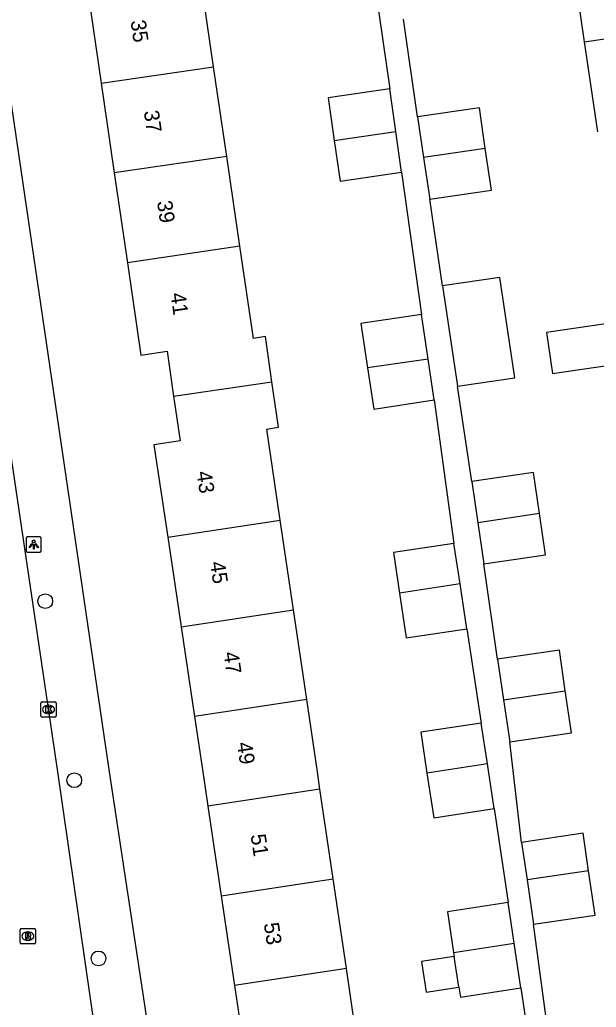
# Model space of a CAD drawing. Extents: x 159053 to 160041, y 380450 to 381422.
# Drawn here: x 159329.7 to 159367.8, y 380984.4 to 381049.8 of the extents above; entities that cross this region are included whole.
import ezdxf

# ---------------------------------------------------------------- set-up
doc = ezdxf.new("R2010")
doc.units = 0
for name, color, linetype in [('IMGEO_Boom', 7, 'Continuous'), ('IMGEO_Kolk', 7, 'Continuous'), ('IMGEO_Lichtpunt', 7, 'Continuous'), ('IMGEO_Pand', 7, 'Continuous'), ('IMGEO_Pand_nummerreeks', 7, 'Continuous'), ('IMGEO_Rijbaan_lokaal_open', 7, 'Continuous'), ('IMGEO_Rioolput', 7, 'Continuous'), ('IMGEO_Voetpad_open', 7, 'Continuous')]:
    doc.layers.add(name, color=color, linetype=linetype)

msp = doc.modelspace()

# ---------------------------------------------------------------- linework, layer by layer
at = {"layer": 'IMGEO_Boom'}
for centre in [(159331.342, 381011.301), (159333.264, 380999.452), (159334.871, 380987.659)]:
    msp.add_circle(centre, 0.489, dxfattribs=at)
at = {"layer": 'IMGEO_Kolk'}
for p, q in [((159331.061, 381003.707), (159331.061, 381004.559)), ((159331.136, 381004.633), (159331.988, 381004.633)), ((159331.549, 381004.413), (159331.574, 381004.413)), ((159332.062, 381004.559), (159332.062, 381003.707)), ((159331.572, 381003.853), (159331.547, 381003.853)), ((159331.988, 381003.633), (159331.136, 381003.633))]:
    msp.add_line(p, q, dxfattribs=at)
for points in [[(159331.061, 381003.707), (159331.061, 381004.559)], [(159331.136, 381004.633), (159331.988, 381004.633)], [(159331.382, 381004.333), (159331.505, 381004.333), (159331.505, 381004.182), (159331.635, 381004.333), (159331.799, 381004.333), (159331.653, 381004.182), (159331.806, 381003.933), (159331.654, 381003.933), (159331.569, 381004.097), (159331.505, 381004.03), (159331.505, 381003.933), (159331.382, 381003.933), (159331.382, 381004.333)], [(159332.062, 381004.559), (159332.062, 381003.707)], [(159331.988, 381003.633), (159331.136, 381003.633)]]:
    msp.add_lwpolyline(points, dxfattribs=at)
for centre, start, end in [((159331.138, 381004.557), 91.55205, 178.44795), ((159331.138, 381004.557), 91.55205, 178.44795), ((159331.986, 381004.557), 1.55205, 88.44795), ((159331.986, 381004.557), 1.55205, 88.44795), ((159331.138, 381003.709), 181.55205, 268.44795), ((159331.138, 381003.709), 181.55205, 268.44795), ((159331.986, 381003.709), 271.55205, 358.44795), ((159331.986, 381003.709), 271.55205, 358.44795)]:
    msp.add_arc(centre, 0.0765, start, end, dxfattribs=at)
for centre, major_axis, ratio, start_param, end_param in [((159331.548, 381004.133), (-0.387, 0.002), 0.722429, 4.712389, 7.853982), ((159331.573, 381004.133), (-0.39, 0.002), 0.717154, 1.570796, 4.712389)]:
    msp.add_ellipse(centre, major_axis=major_axis, ratio=ratio, start_param=start_param, end_param=end_param, dxfattribs=at)
at = {"layer": 'IMGEO_Lichtpunt'}
for p, q in [((159330.084, 381015.453), (159330.084, 381014.646)), ((159330.084, 381015.453), (159330.084, 381014.646)), ((159330.986, 381015.548), (159330.178, 381015.548)), ((159330.986, 381015.548), (159330.178, 381015.548)), ((159331.08, 381014.646), (159331.08, 381015.453)), ((159331.08, 381014.646), (159331.08, 381015.453)), ((159330.178, 381014.552), (159330.986, 381014.552)), ((159330.178, 381014.552), (159330.986, 381014.552))]:
    msp.add_line(p, q, dxfattribs=at)
for points in [[(159330.458, 381015.117), (159330.497, 381015.089), (159330.309, 381014.827), (159330.271, 381014.854), (159330.458, 381015.117)], [(159330.56, 381015.069), (159330.607, 381015.069), (159330.607, 381014.747), (159330.56, 381014.747), (159330.56, 381015.069)], [(159330.67, 381015.089), (159330.708, 381015.116), (159330.895, 381014.854), (159330.856, 381014.826), (159330.67, 381015.089)]]:
    msp.add_lwpolyline(points, dxfattribs=at)
msp.add_circle((159330.583, 381015.251), 0.0994, dxfattribs=at)
for centre, start, end in [((159330.178, 381015.453), 90, 180), ((159330.178, 381015.453), 90, 180), ((159330.986, 381015.453), 0, 90), ((159330.986, 381015.453), 0, 90), ((159330.178, 381014.646), 180, 270), ((159330.178, 381014.646), 180, 270), ((159330.986, 381014.646), 270, 0), ((159330.986, 381014.646), 270, 360)]:
    msp.add_arc(centre, 0.0946, start, end, dxfattribs=at)
at = {"layer": 'IMGEO_Pand'}
for points in [[(159366.155, 381054.257), (159367.026, 381048.302)], [(159342.489, 381046.664), (159341.62, 381052.601)], [(159334.178, 381051.506), (159335.047, 381045.569)], [(159367.026, 381048.302), (159374.491, 381049.393)], [(159367.026, 381048.302), (159367.898, 381042.344)], [(159335.047, 381045.569), (159342.489, 381046.664)], [(159343.358, 381040.727), (159342.489, 381046.664)], [(159335.047, 381045.569), (159335.916, 381039.632)], [(159354.151, 381045.198), (159350.069, 381044.601), (159350.482, 381041.775)], [(159354.553, 381042.375), (159354.151, 381045.198)], [(159360.479, 381041.259), (159360.084, 381043.953), (159355.997, 381043.355)], [(159355.997, 381043.355), (159356.392, 381040.661)], [(159350.482, 381041.775), (159354.553, 381042.375)], [(159354.937, 381039.685), (159354.553, 381042.375)], [(159350.482, 381041.775), (159350.874, 381039.091), (159354.937, 381039.685)], [(159360.479, 381041.259), (159356.392, 381040.661)], [(159356.797, 381037.893), (159360.884, 381038.491), (159360.479, 381041.259)], [(159343.358, 381040.727), (159335.916, 381039.632)], [(159344.226, 381034.79), (159343.358, 381040.727)], [(159356.392, 381040.661), (159356.797, 381037.893)], [(159335.916, 381039.632), (159336.784, 381033.695)], [(159344.226, 381034.79), (159336.784, 381033.695)], [(159346.351, 381025.823), (159345.915, 381028.807), (159345.122, 381028.669), (159344.226, 381034.79)], [(159336.784, 381033.695), (159337.678, 381027.588), (159339.41, 381027.841), (159339.845, 381024.87)], [(159358.638, 381025.52), (159362.433, 381026.084), (159361.445, 381032.719), (159357.651, 381032.154)], [(159357.651, 381032.154), (159358.638, 381025.52)], [(159356.246, 381030.271), (159352.237, 381029.663), (159352.68, 381026.738)], [(159356.693, 381027.322), (159356.246, 381030.271)], [(159364.525, 381029.082), (159364.924, 381026.356), (159368.849, 381026.931), (159368.449, 381029.657), (159364.525, 381029.082)], [(159356.693, 381027.322), (159352.68, 381026.738)], [(159357.102, 381024.623), (159356.693, 381027.322)], [(159352.68, 381026.738), (159353.093, 381024.015), (159357.102, 381024.623)], [(159339.845, 381024.87), (159346.351, 381025.823)], [(159346.907, 381016.663), (159346.019, 381022.69), (159346.793, 381022.804), (159346.351, 381025.823)], [(159339.845, 381024.87), (159340.28, 381021.899), (159338.541, 381021.645), (159339.452, 381015.535)], [(159364.062, 381017.095), (159363.662, 381019.824), (159359.575, 381019.226)], [(159359.575, 381019.226), (159359.978, 381016.477)], [(159364.062, 381017.095), (159359.978, 381016.477)], [(159360.375, 381013.764), (159364.462, 381014.362), (159364.062, 381017.095)], [(159339.452, 381015.535), (159346.907, 381016.663)], [(159347.781, 381010.728), (159346.907, 381016.663)], [(159359.978, 381016.477), (159360.375, 381013.764)], [(159339.452, 381015.535), (159340.336, 381009.601)], [(159358.4, 381015.126), (159354.391, 381014.518), (159354.798, 381011.832)], [(159358.807, 381012.441), (159358.4, 381015.126)], [(159358.807, 381012.441), (159354.798, 381011.832)], [(159359.256, 381009.478), (159358.807, 381012.441)], [(159354.798, 381011.832), (159355.247, 381008.87), (159359.256, 381009.478)], [(159340.336, 381009.601), (159347.781, 381010.728)], [(159348.655, 381004.791), (159347.781, 381010.728)], [(159340.336, 381009.601), (159341.221, 381003.666)], [(159365.773, 381005.365), (159365.379, 381008.054), (159361.292, 381007.456)], [(159361.292, 381007.456), (159361.685, 381004.77)], [(159361.685, 381004.77), (159365.773, 381005.365)], [(159362.092, 381001.994), (159366.179, 381002.592), (159365.773, 381005.365)], [(159348.655, 381004.791), (159341.221, 381003.666)], [(159349.53, 380998.855), (159349.361, 381000), (159348.655, 381004.791)], [(159361.685, 381004.77), (159362.092, 381001.994)], [(159341.221, 381003.666), (159341.767, 381000), (159342.105, 380997.732)], [(159360.212, 381003.229), (159356.203, 381002.621), (159356.611, 380999.926)], [(159360.621, 381000.532), (159360.212, 381003.229)], [(159360.621, 381000.532), (159356.611, 380999.926)], [(159361.068, 380997.581), (159360.621, 381000.532)], [(159356.611, 380999.926), (159357.059, 380996.973), (159361.068, 380997.581)], [(159349.53, 380998.855), (159342.105, 380997.732)], [(159350.404, 380992.919), (159349.53, 380998.855)], [(159342.105, 380997.732), (159342.99, 380991.797)], [(159367.313, 380993.463), (159366.947, 380995.943), (159362.878, 380995.342)], [(159362.878, 380995.342), (159363.243, 380992.871)], [(159367.313, 380993.463), (159363.243, 380992.871)], [(159363.679, 380989.924), (159367.748, 380990.525), (159367.313, 380993.463)], [(159342.99, 380991.797), (159350.404, 380992.919)], [(159351.278, 380986.983), (159350.404, 380992.919)], [(159363.243, 380992.871), (159363.679, 380989.924)], [(159342.99, 380991.797), (159343.874, 380985.863)], [(159361.981, 380991.36), (159357.972, 380990.752), (159358.38, 380988.057)], [(159362.39, 380988.664), (159361.981, 380991.36)], [(159358.38, 380988.057), (159362.39, 380988.664)], [(159362.837, 380985.712), (159362.39, 380988.664)], [(159358.38, 380988.057), (159358.422, 380987.778)], [(159358.422, 380987.778), (159356.264, 380987.451), (159356.57, 380985.434), (159358.728, 380985.762)], [(159358.728, 380985.762), (159358.422, 380987.778)], [(159351.278, 380986.983), (159343.874, 380985.863)], [(159352.153, 380981.047), (159351.278, 380986.983)], [(159343.874, 380985.863), (159344.758, 380979.928)], [(159358.728, 380985.762), (159358.828, 380985.104), (159362.837, 380985.712)]]:
    msp.add_lwpolyline(points, dxfattribs=at)
at = {"layer": 'IMGEO_Rijbaan_lokaal_open'}
msp.add_lwpolyline([(159334.965, 380980.773), (159334.351, 380985.012), (159332.172, 381000), (159327.968, 381028.382)], dxfattribs=at)
at = {"layer": 'IMGEO_Rioolput'}
for p, q in [((159329.693, 380988.706), (159329.693, 380989.558)), ((159329.768, 380989.632), (159330.62, 380989.632)), ((159330.181, 380989.412), (159330.206, 380989.412)), ((159330.694, 380989.558), (159330.694, 380988.706)), ((159330.62, 380988.632), (159329.768, 380988.632)), ((159330.204, 380988.852), (159330.179, 380988.852))]:
    msp.add_line(p, q, dxfattribs=at)
for points in [[(159329.693, 380988.706), (159329.693, 380989.558)], [(159329.768, 380989.632), (159330.62, 380989.632)], [(159330.282, 380989.33), (159330.03, 380989.332), (159330.03, 380988.932)], [(159330.694, 380989.558), (159330.694, 380988.706)], [(159330.62, 380988.632), (159329.768, 380988.632)], [(159330.03, 380988.932), (159330.154, 380988.932), (159330.154, 380989.094), (159330.165, 380989.094)], [(159330.208, 380989.251), (159330.154, 380989.251), (159330.154, 380989.17)], [(159330.154, 380989.17), (159330.206, 380989.17)], [(159330.212, 380989.065), (159330.283, 380988.932), (159330.423, 380988.932), (159330.358, 380989.058)]]:
    msp.add_lwpolyline(points, dxfattribs=at)
for centre, radius, start, end in [((159329.77, 380989.556), 0.0765, 91.55205, 178.44795), ((159329.77, 380989.556), 0.0765, 91.55205, 178.44795), ((159330.281, 380989.22), 0.109, 350.36119, 89.41601), ((159330.618, 380989.556), 0.0765, 1.55205, 88.44795), ((159330.618, 380989.556), 0.0765, 1.55205, 88.44795), ((159329.77, 380988.708), 0.0765, 181.55205, 268.44795), ((159329.77, 380988.708), 0.0765, 181.55205, 268.44795), ((159330.164, 380989.041), 0.0533, 26.02933, 88.69889), ((159330.19, 380989.359), 0.19, 274.7715, 282.96867), ((159330.214, 380989.155), 0.0964, 77.00612, 93.18647), ((159330.228, 380989.212), 0.0378, 276.66336, 79.67722), ((159330.279, 380989.22), 0.112, 277.58423, 350.98172), ((159330.263, 380989.005), 0.108, 29.51342, 73.79051), ((159330.618, 380988.708), 0.0765, 271.55205, 358.44795), ((159330.618, 380988.708), 0.0765, 271.55205, 358.44795)]:
    msp.add_arc(centre, radius, start, end, dxfattribs=at)
for centre, major_axis, ratio, start_param, end_param in [((159330.18, 380989.132), (-0.387, 0.002), 0.722429, 4.712389, 7.853982), ((159330.205, 380989.132), (-0.39, 0.002), 0.717154, 1.570796, 4.712389)]:
    msp.add_ellipse(centre, major_axis=major_axis, ratio=ratio, start_param=start_param, end_param=end_param, dxfattribs=at)
at = {"layer": 'IMGEO_Voetpad_open'}
for points in [[(159323.886, 381079.531), (159335.584, 381000), (159340.592, 380966.957)], [(159353.257, 381051.468), (159354.151, 381045.198)], [(159355.997, 381043.355), (159355.054, 381049.806)], [(159354.937, 381039.685), (159356.246, 381030.271)], [(159357.651, 381032.154), (159356.797, 381037.893)], [(159359.575, 381019.226), (159358.638, 381025.52)], [(159357.102, 381024.623), (159358.4, 381015.126)], [(159361.292, 381007.456), (159360.375, 381013.764)], [(159359.256, 381009.478), (159360.212, 381003.229)], [(159362.878, 380995.342), (159362.092, 381001.994)], [(159361.068, 380997.581), (159361.981, 380991.36)], [(159366.011, 380972.559), (159363.679, 380989.924)], [(159362.837, 380985.712), (159363.75, 380979.491)]]:
    msp.add_lwpolyline(points, dxfattribs=at)

# ---------------------------------------------------------------- texts
at = {"layer": 'IMGEO_Pand_nummerreeks'}
for s, rotation, p in [('35', 278.32417, (159336.991, 381049.688)), ('37', 278.32417, (159337.865, 381043.712)), ('39', 278.32417, (159338.74, 381037.736)), ('41', 278.32417, (159339.63, 381031.647)), ('43', 278.47701, (159341.358, 381019.844)), ('45', 278.47701, (159342.249, 381013.866)), ('47', 278.47701, (159343.14, 381007.888)), ('49', 278.47701, (159344.031, 381001.91)), ('51', 278.47675, (159344.937, 380995.825)), ('53', 278.47675, (159345.811, 380989.967))]:
    msp.add_text(s, height=1, rotation=rotation, dxfattribs=at).set_placement(p)

doc.saveas('drawing.dxf')
